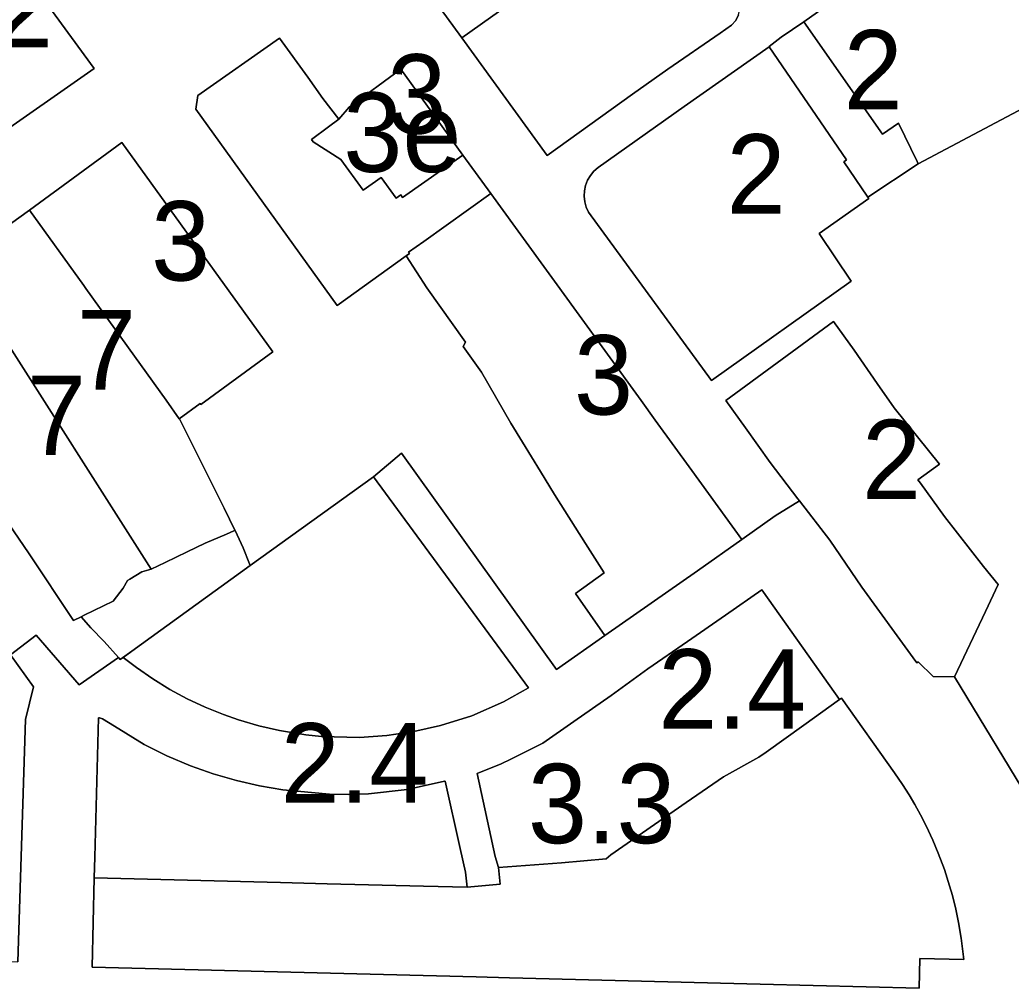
# Model space of a CAD drawing. Extents: x 598968 to 613553, y 4409678 to 4430833.
# Drawn here: x 608408.5 to 608558.2, y 4415517.6 to 4415663.9 of the extents above; entities that cross this region are included whole.
import ezdxf

# ---------------------------------------------------------------- set-up
doc = ezdxf.new("R2010")
doc.units = 0
for name, color, linetype in [('1', 7, 'Continuous'), ('SUBZONA 3e. EDIFICIS ENTRE MITGERES amb projecte especial', 7, 'Continuous'), ('ZONA 2. CARRERS DE CASES. Cases de trast', 7, 'Continuous'), ('ZONA 2.4. Ciutat jardí de mitja densitat - ANNEX III B', 7, 'Continuous'), ("ZONA 3. ILLES  D'EDIFICIS ENTRE MITGERES. EIXAMPLE.", 7, 'Continuous'), ('ZONA 3.3. Volumentría específica - ANNEX III B', 7, 'Continuous'), ('ZONA 7. CONJUNTS AMB ORDENACIONS ESPECÍFIQUES', 7, 'Continuous')]:
    doc.layers.add(name, color=color, linetype=linetype)

msp = doc.modelspace()

# ---------------------------------------------------------------- linework, layer by layer
at = {"layer": '1'}
for points in [[(608577.6388, 4415659.9159), (608549.2018, 4415644.867), (608544.1993, 4415642.2056), (608536.5794, 4415637.1455), (608536.7294, 4415636.9255), (608529.2138, 4415631.6551), (608534.0795, 4415624.4556), (608512.9448, 4415609.431), (608494.3783, 4415634.9), (608494.0303, 4415635.656), (608493.8074, 4415636.4581), (608493.7155, 4415637.2854), (608493.7569, 4415638.1168), (608493.9304, 4415638.931), (608494.2317, 4415639.7069), (608494.6531, 4415640.4248), (608495.1837, 4415641.0662), (608495.8099, 4415641.6147), (608508.8297, 4415650.8348), (608521.6796, 4415659.8749), (608521.6445, 4415659.9242), (608523.4795, 4415661.315), (608526.8877, 4415663.6594), (608562.4889, 4415688.8653)], [(608406.94, 4415674.051), (608419.7052, 4415656.5679), (608403.8649, 4415645.5793)], [(608517.0296, 4415664.7148), (608516.6096, 4415663.8448), (608515.9796, 4415663.1148), (608514.2592, 4415661.9502), (608506.3597, 4415656.4647), (608500.9998, 4415652.6847), (608488.13, 4415643.4645), (608475.2401, 4415661.2041), (608471.9401, 4415665.694)], [(608393.1412, 4415623.1231), (608409.911, 4415635.1932), (608423.8454, 4415645.4183), (608446.6784, 4415613.7497), (608435.8207, 4415605.8141), (608435.7007, 4415605.974), (608432.5334, 4415603.6723), (608432.5608, 4415603.634), (608439.3042, 4415590.1703), (608440.9603, 4415586.8244), (608440.9807, 4415586.7844), (608442.1907, 4415584.1344), (608443.1634, 4415581.7406), (608443.2718, 4415581.4737), (608461.8989, 4415594.8671), (608466.1134, 4415598.4495), (608489.5384, 4415565.76), (608496.8607, 4415570.898), (608492.3883, 4415577.2701), (608496.7401, 4415580.3855), (608493.9401, 4415584.8054), (608489.2501, 4415592.1952), (608487.1302, 4415595.6751), (608484.4202, 4415600.115), (608482.6602, 4415602.9749), (608478.2302, 4415610.6848), (608475.4502, 4415614.5847), (608475.8002, 4415615.2147), (608469.9703, 4415623.4645), (608466.8046, 4415628.2779), (608456.4211, 4415620.7551), (608435.031, 4415650.4227), (608435.3561, 4415652.5076), (608447.7078, 4415661.1547), (608451.9709, 4415655.2582), (608454.2209, 4415652.0758), (608456.6472, 4415648.9082), (608458.2303, 4415650.7539), (608466.0078, 4415656.4649), (608475.4099, 4415643.5032), (608479.6253, 4415637.6917), (608483.3374, 4415632.5741), (608489.2443, 4415624.4307), (608492.5483, 4415619.8759), (608497.2246, 4415613.4291), (608502.3143, 4415606.4122), (608504.4632, 4415603.4498), (608509.9763, 4415595.8494), (608517.559, 4415585.3959), (608522.578, 4415589.0107), (608526.2553, 4415591.2499), (608526.0044, 4415591.5766), (608521.8111, 4415597.0643), (608518.1051, 4415602.2913), (608515.1298, 4415606.4055), (608531.3795, 4415618.3656), (608534.4895, 4415614.0057), (608537.9818, 4415608.9878), (608540.5594, 4415605.286), (608547.3794, 4415596.8162), (608544.1494, 4415594.4262), (608544.5095, 4415593.9361), (608548.1516, 4415588.9013), (608554.0694, 4415581.3265), (608556.2593, 4415578.6266), (608554.3494, 4415574.5266), (608549.6895, 4415564.6566), (608561.6906, 4415544.8385)], [(608407.0624, 4415567.9754), (608410.9188, 4415570.9362), (608417.4451, 4415563.4776), (608423.3408, 4415567.6004), (608421.191, 4415570.0042), (608419.181, 4415572.0742), (608417.7298, 4415573.754), (608416.5811, 4415573.1941), (608409.8611, 4415583.2539), (608390.7884, 4415611.1929)], [(608561.6906, 4415544.8385), (608549.6895, 4415564.6566), (608546.4295, 4415564.7266), (608544.1995, 4415566.9165), (608543.9735, 4415566.7568), (608543.4295, 4415567.5265), (608541.0148, 4415570.853), (608535.6862, 4415578.2152), (608530.8306, 4415585.2916), (608526.2553, 4415591.2499), (608522.578, 4415589.0107), (608517.559, 4415585.3959), (608510.8628, 4415580.7043), (608496.8607, 4415570.898), (608489.5384, 4415565.76), (608466.1134, 4415598.4495), (608461.8989, 4415594.8671), (608485.3215, 4415562.9869), (608481.5215, 4415560.8768), (608476.7416, 4415558.7868), (608472.0017, 4415557.2967), (608467.9817, 4415556.3966), (608463.9118, 4415555.7866), (608459.7968, 4415555.5115), (608454.0319, 4415555.6464), (608451.6469, 4415555.8964), (608447.692, 4415556.5363), (608444.572, 4415557.2562), (608441.492, 4415558.1561), (608439.222, 4415558.9461), (608436.4421, 4415560.076), (608433.7221, 4415561.346), (608431.1221, 4415562.7459), (608428.5422, 4415564.3358), (608426.0822, 4415566.0608), (608424.0622, 4415567.5657), (608425.4005, 4415568.5346), (608423.6378, 4415567.2682), (608423.3964, 4415567.5382), (608423.3408, 4415567.6004), (608417.4451, 4415563.4776), (608410.9188, 4415570.9362), (608407.0624, 4415567.9754), (608410.5324, 4415563.1655), (608409.3024, 4415558.1956), (608408.1425, 4415521.596)]]:
    msp.add_lwpolyline(points, dxfattribs=at)
for points in [[(608425.4005, 4415568.5346), (608424.0622, 4415567.5657), (608426.0822, 4415566.0608), (608428.5422, 4415564.3358), (608431.1221, 4415562.7459), (608433.7221, 4415561.346), (608436.4421, 4415560.076), (608439.222, 4415558.9461), (608441.492, 4415558.1561), (608444.572, 4415557.2562), (608447.692, 4415556.5363), (608451.6469, 4415555.8964), (608454.0319, 4415555.6464), (608459.7968, 4415555.5115), (608463.9118, 4415555.7866), (608467.9817, 4415556.3966), (608472.0017, 4415557.2967), (608476.7416, 4415558.7868), (608481.5215, 4415560.8768), (608485.3215, 4415562.9869), (608461.8989, 4415594.8671), (608443.2718, 4415581.4737), (608443.2674, 4415581.4705)], [(608405.5358, 4415566.9639), (608400.7913, 4415563.4339), (608388.2915, 4415556.6838), (608388.2605, 4415556.7696), (608388.2527, 4415556.7652), (608387.3627, 4415559.1751), (608385.2102, 4415564.5075), (608383.2527, 4415569.6049), (608381.6127, 4415575.0248), (608380.6827, 4415579.9448), (608380.1461, 4415587.1097), (608379.6024, 4415587.7816), (608379.2517, 4415587.6284), (608367.8302, 4415585.857), (608367.8304, 4415522.7202), (608371.923, 4415522.4853), (608408.1425, 4415521.596), (608409.3024, 4415558.1956), (608410.5324, 4415563.1655), (608407.0624, 4415567.9754), (608406.2224, 4415567.4554)], [(608443.2718, 4415581.4737), (608443.1634, 4415581.7406), (608442.1907, 4415584.1344), (608440.9807, 4415586.7844), (608440.7969, 4415586.7057), (608439.6702, 4415586.2231), (608436.4761, 4415584.855), (608433.7414, 4415583.5403), (608430.4009, 4415581.9342), (608428.3066, 4415580.9541), (608426.9109, 4415580.5342), (608425.0668, 4415579.4278), (608424.711, 4415579.2142), (608424.0465, 4415578.0797), (608422.551, 4415576.1042), (608418.1714, 4415573.9693), (608417.7298, 4415573.754), (608419.181, 4415572.0742), (608421.191, 4415570.0042), (608423.3408, 4415567.6004), (608423.3964, 4415567.5382), (608423.6378, 4415567.2682), (608425.4005, 4415568.5346), (608443.2674, 4415581.4705)], [(608532.3165, 4415561.2214), (608532.6085, 4415561.4289), (608540.615, 4415550.1784), (608541.8336, 4415548.3914), (608542.8244, 4415546.8246), (608543.6687, 4415545.3957), (608544.5395, 4415543.816), (608545.4002, 4415542.13), (608546.4091, 4415539.9595), (608547.2229, 4415538.0148), (608548.1457, 4415535.5282), (608548.9312, 4415533.0795), (608549.349, 4415531.5986), (608549.8522, 4415529.5757), (608550.2859, 4415527.5182), (608550.6891, 4415525.1554), (608551.078, 4415521.9455), (608544.43, 4415522.1147), (608544.3155, 4415517.6161), (608520.3236, 4415518.2265), (608482.4144, 4415519.1909), (608477.3771, 4415519.319), (608419.3652, 4415520.7947), (608419.7088, 4415534.2902), (608419.7878, 4415537.3987), (608420.3241, 4415558.4667), (608420.4919, 4415558.4609), (608420.6573, 4415558.4326), (608420.8174, 4415558.3823), (608420.9693, 4415558.3108), (608422.7372, 4415557.2111), (608427.2623, 4415554.4574), (608430.6879, 4415552.7249), (608434.2201, 4415551.2219), (608437.6792, 4415549.9969), (608441.2031, 4415548.9732), (608444.6856, 4415548.1729), (608448.2075, 4415547.5693), (608455.2317, 4415546.9399), (608458.152, 4415546.8601), (608461.1322, 4415546.9656), (608466.9834, 4415547.6328), (608472.6234, 4415548.872), (608472.7339, 4415548.9024), (608475.0019, 4415538.7418), (608475.8083, 4415535.1293), (608476.0337, 4415532.8574), (608481.0092, 4415533.3512), (608480.76, 4415535.8621), (608480.2672, 4415537.5007), (608477.5272, 4415550.0305), (608481.1772, 4415551.5305), (608482.6214, 4415552.2326), (608487.4971, 4415554.6506), (608492.1609, 4415557.9172), (608497.7769, 4415561.8507), (608503.3569, 4415565.8508), (608509.3366, 4415570.0004), (608515.0877, 4415573.9917), (608520.5766, 4415577.8009), (608527.6365, 4415567.7912)]]:
    msp.add_lwpolyline(points, close=True, dxfattribs=at)
at = {"layer": 'SUBZONA 3e. EDIFICIS ENTRE MITGERES amb projecte especial'}
msp.add_lwpolyline([(608456.6472, 4415648.9082), (608454.2209, 4415652.0758), (608451.9709, 4415655.2582), (608447.7078, 4415661.1547), (608435.3561, 4415652.5076), (608435.031, 4415650.4227), (608456.4211, 4415620.7551), (608466.8046, 4415628.2779), (608467.3104, 4415628.6444), (608467.182, 4415628.8255), (608469.4741, 4415630.4587), (608479.6253, 4415637.6917), (608475.4099, 4415643.5032), (608466.2803, 4415637.1042), (608466.0103, 4415637.4942), (608465.3003, 4415637.0032), (608463.0296, 4415640.1336), (608460.343, 4415638.1873), (608456.9404, 4415642.824), (608452.7604, 4415645.5039), (608452.5181, 4415645.8394), (608455.0904, 4415647.7539)], close=True, dxfattribs=at)
at = {"layer": 'ZONA 2. CARRERS DE CASES. Cases de trast'}
for points in [[(608544.1993, 4415642.2056), (608549.2018, 4415644.867), (608577.6388, 4415659.9159), (608574.9189, 4415664.5958), (608576.1088, 4415665.2859), (608571.5688, 4415673.0591), (608573.0889, 4415674.0457), (608573.6388, 4415673.2857), (608589.3786, 4415684.5559), (608606.3484, 4415702.8959), (608596.5583, 4415713.3348), (608578.2187, 4415700.2455), (608579.5587, 4415698.3255), (608563.8489, 4415686.9654), (608562.4889, 4415688.8653), (608526.8877, 4415663.6594), (608538.8058, 4415646.6475), (608541.1893, 4415648.3254), (608544.0449, 4415642.5196)], [(608475.2401, 4415661.2041), (608488.13, 4415643.4645), (608500.9998, 4415652.6847), (608506.3597, 4415656.4647), (608514.2592, 4415661.9502), (608515.9796, 4415663.1148), (608516.6096, 4415663.8448), (608517.0296, 4415664.7148), (608517.1396, 4415665.1448), (608517.2096, 4415665.6548), (608517.1496, 4415666.6148), (608516.8496, 4415667.5248), (608516.4178, 4415668.1656), (608509.2496, 4415678.8045), (608505.0097, 4415684.9843), (608502.3697, 4415683.2343), (608499.2498, 4415681.1843), (608500.3897, 4415679.6243), (608501.4897, 4415678.1243), (608499.1201, 4415672.2043), (608498.4798, 4415670.6044), (608496.7998, 4415666.4044), (608492.0099, 4415673.2242), (608483.92, 4415667.4042)], [(608403.6097, 4415645.5), (608403.8649, 4415645.5793), (608419.7052, 4415656.5679), (608406.94, 4415674.051), (608406.7109, 4415674.1127), (608389.3811, 4415661.0925), (608395.714, 4415652.6079), (608395.7448, 4415652.6311), (608397.7489, 4415654.1331), (608397.7601, 4415654.1175), (608399.1543, 4415652.1675)], [(608544.1993, 4415642.2056), (608544.0449, 4415642.5196), (608541.1893, 4415648.3254), (608538.8058, 4415646.6475), (608526.8877, 4415663.6594), (608523.4795, 4415661.315), (608521.6445, 4415659.9242), (608521.6796, 4415659.8749), (608533.3394, 4415642.8054), (608532.9694, 4415642.4854), (608536.4897, 4415637.2781), (608536.5794, 4415637.1455)], [(608536.5794, 4415637.1455), (608536.4897, 4415637.2781), (608532.9694, 4415642.4854), (608533.3394, 4415642.8054), (608521.6796, 4415659.8749), (608508.8297, 4415650.8348), (608495.8099, 4415641.6147), (608495.1837, 4415641.0662), (608494.6531, 4415640.4248), (608494.2317, 4415639.7069), (608493.9304, 4415638.931), (608493.7569, 4415638.1168), (608493.7155, 4415637.2854), (608493.8074, 4415636.4581), (608494.0303, 4415635.656), (608494.3783, 4415634.9), (608512.9448, 4415609.431), (608534.0795, 4415624.4556), (608529.2138, 4415631.6551), (608536.7294, 4415636.9255)], [(608549.6895, 4415564.6566), (608554.3494, 4415574.5266), (608556.2593, 4415578.6266), (608554.0694, 4415581.3265), (608548.1516, 4415588.9013), (608544.5095, 4415593.9361), (608544.1494, 4415594.4262), (608547.3794, 4415596.8162), (608540.5594, 4415605.286), (608537.9818, 4415608.9878), (608534.4895, 4415614.0057), (608531.3795, 4415618.3656), (608515.1298, 4415606.4055), (608518.1051, 4415602.2913), (608521.8111, 4415597.0643), (608526.0044, 4415591.5766), (608526.2553, 4415591.2499), (608530.8306, 4415585.2916), (608535.6862, 4415578.2152), (608541.0148, 4415570.853), (608543.4295, 4415567.5265), (608543.9735, 4415566.7568), (608544.1995, 4415566.9165), (608546.4295, 4415564.7266)]]:
    msp.add_lwpolyline(points, close=True, dxfattribs=at)
at = {"layer": 'ZONA 2.4. Ciutat jardí de mitja densitat - ANNEX III B'}
for points in [[(608532.3165, 4415561.2214), (608527.6365, 4415567.7912), (608520.5766, 4415577.8009), (608515.0877, 4415573.9917), (608509.3366, 4415570.0004), (608503.3569, 4415565.8508), (608497.7769, 4415561.8507), (608492.1609, 4415557.9172), (608487.4971, 4415554.6506), (608482.6214, 4415552.2326), (608481.1772, 4415551.5305), (608477.5272, 4415550.0305), (608480.2672, 4415537.5007), (608480.76, 4415535.8621), (608490.2771, 4415536.5709), (608497.017, 4415537.141), (608497.737, 4415537.761), (608509.1469, 4415545.6511), (608514.7568, 4415549.5412), (608520.1261, 4415552.5221), (608521.2128, 4415553.2963), (608526.9105, 4415557.3629)], [(608476.0337, 4415532.8574), (608475.8083, 4415535.1293), (608475.0019, 4415538.7418), (608472.7339, 4415548.9024), (608472.6234, 4415548.872), (608466.9834, 4415547.6328), (608461.1322, 4415546.9656), (608458.152, 4415546.8601), (608455.2317, 4415546.9399), (608448.2075, 4415547.5693), (608444.6856, 4415548.1729), (608441.2031, 4415548.9732), (608437.6792, 4415549.9969), (608434.2201, 4415551.2219), (608430.6879, 4415552.7249), (608427.2623, 4415554.4574), (608422.7372, 4415557.2111), (608420.9693, 4415558.3108), (608420.8174, 4415558.3823), (608420.6573, 4415558.4326), (608420.4919, 4415558.4609), (608420.3241, 4415558.4667), (608419.7878, 4415537.3987), (608419.7088, 4415534.2902), (608433.78, 4415533.9323), (608447.8513, 4415533.5743), (608454.8869, 4415533.3953), (608469.4217, 4415533.0256)]]:
    msp.add_lwpolyline(points, close=True, dxfattribs=at)
at = {"layer": "ZONA 3. ILLES  D'EDIFICIS ENTRE MITGERES. EIXAMPLE."}
for points in [[(608505.0097, 4415684.9843), (608503.4297, 4415687.3043), (608501.6021, 4415690.0048), (608499.5659, 4415693.0136), (608497.693, 4415695.722), (608466.8746, 4415674.5267), (608466.7902, 4415673.9238), (608466.7886, 4415673.4447), (608466.8202, 4415673.0238), (608466.8902, 4415672.6338), (608467.3756, 4415671.9611), (608468.8601, 4415669.9039), (608471.9401, 4415665.694), (608475.2401, 4415661.2041), (608483.92, 4415667.4042), (608492.0099, 4415673.2242), (608496.7998, 4415666.4044), (608498.4798, 4415670.6044), (608499.1201, 4415672.2043), (608501.4897, 4415678.1243), (608500.3897, 4415679.6243), (608499.2498, 4415681.1843), (608502.3697, 4415683.2343)], [(608475.4099, 4415643.5032), (608466.0078, 4415656.4649), (608458.2303, 4415650.7539), (608456.6472, 4415648.9082), (608455.0904, 4415647.7539), (608452.5181, 4415645.8394), (608452.7604, 4415645.5039), (608456.9404, 4415642.824), (608460.343, 4415638.1873), (608463.0296, 4415640.1336), (608465.3003, 4415637.0032), (608466.0103, 4415637.4942), (608466.2803, 4415637.1042)], [(608432.5334, 4415603.6723), (608435.7007, 4415605.974), (608435.8207, 4415605.8141), (608446.6784, 4415613.7497), (608423.8454, 4415645.4183), (608409.911, 4415635.1932), (608418.1505, 4415623.7733), (608418.446, 4415623.3635), (608422.8103, 4415617.2633), (608430.5408, 4415606.4539)], [(608517.559, 4415585.3959), (608509.9763, 4415595.8494), (608504.4632, 4415603.4498), (608502.3143, 4415606.4122), (608497.2246, 4415613.4291), (608492.5483, 4415619.8759), (608489.2443, 4415624.4307), (608483.3374, 4415632.5741), (608479.6253, 4415637.6917), (608469.4741, 4415630.4587), (608467.182, 4415628.8255), (608467.3104, 4415628.6444), (608466.8046, 4415628.2779), (608469.9703, 4415623.4645), (608475.8002, 4415615.2147), (608475.4502, 4415614.5847), (608478.2302, 4415610.6848), (608482.6602, 4415602.9749), (608484.4202, 4415600.115), (608487.1302, 4415595.6751), (608489.2501, 4415592.1952), (608493.9401, 4415584.8054), (608496.7401, 4415580.3855), (608492.3883, 4415577.2701), (608496.8607, 4415570.898), (608510.8628, 4415580.7043)]]:
    msp.add_lwpolyline(points, close=True, dxfattribs=at)
at = {"layer": 'ZONA 3.3. Volumentría específica - ANNEX III B'}
msp.add_lwpolyline([(608419.7088, 4415534.2902), (608419.3652, 4415520.7947), (608477.3771, 4415519.319), (608482.4144, 4415519.1909), (608520.3236, 4415518.2265), (608544.3155, 4415517.6161), (608544.43, 4415522.1147), (608551.078, 4415521.9455), (608550.6891, 4415525.1554), (608550.2859, 4415527.5182), (608549.8522, 4415529.5757), (608549.349, 4415531.5986), (608548.9312, 4415533.0795), (608548.1457, 4415535.5282), (608547.2229, 4415538.0148), (608546.4091, 4415539.9595), (608545.4002, 4415542.13), (608544.5395, 4415543.816), (608543.6687, 4415545.3957), (608542.8244, 4415546.8246), (608541.8336, 4415548.3914), (608540.615, 4415550.1784), (608532.6085, 4415561.4289), (608532.3165, 4415561.2214), (608526.9105, 4415557.3629), (608521.2128, 4415553.2963), (608520.1261, 4415552.5221), (608514.7568, 4415549.5412), (608509.1469, 4415545.6511), (608497.737, 4415537.761), (608497.017, 4415537.141), (608490.2771, 4415536.5709), (608480.76, 4415535.8621), (608481.0092, 4415533.3512), (608476.0337, 4415532.8574), (608469.4217, 4415533.0256), (608454.8869, 4415533.3953), (608447.8513, 4415533.5743), (608433.78, 4415533.9323)], close=True, dxfattribs=at)
at = {"layer": 'ZONA 7. CONJUNTS AMB ORDENACIONS ESPECÍFIQUES'}
for points in [[(608432.5334, 4415603.6723), (608430.5408, 4415606.4539), (608422.8103, 4415617.2633), (608418.446, 4415623.3635), (608418.1505, 4415623.7733), (608409.911, 4415635.1932), (608393.1412, 4415623.1231), (608397.2142, 4415617.5055), (608397.6888, 4415616.8509), (608404.7162, 4415617.92), (608428.3066, 4415580.9541), (608430.4009, 4415581.9342), (608433.7414, 4415583.5403), (608436.4761, 4415584.855), (608439.6702, 4415586.2231), (608440.7969, 4415586.7057), (608440.9807, 4415586.7844), (608440.9603, 4415586.8244), (608439.3042, 4415590.1703), (608432.5608, 4415603.634)], [(608428.3066, 4415580.9541), (608404.7162, 4415617.92), (608397.6888, 4415616.8509), (608397.2142, 4415617.5055), (608393.1412, 4415623.1231), (608390.7884, 4415611.1929), (608409.8611, 4415583.2539), (608416.5811, 4415573.1941), (608417.7298, 4415573.754), (608418.1714, 4415573.9693), (608422.551, 4415576.1042), (608424.0465, 4415578.0797), (608424.711, 4415579.2142), (608425.0668, 4415579.4278), (608426.9109, 4415580.5342)]]:
    msp.add_lwpolyline(points, close=True, dxfattribs=at)

# ---------------------------------------------------------------- texts
at = {"layer": 'SUBZONA 3e. EDIFICIS ENTRE MITGERES amb projecte especial'}
msp.add_text('3e', height=12, dxfattribs=at).set_placement((608457.3282, 4415640.9549))
at = {"layer": 'ZONA 2. CARRERS DE CASES. Cases de trast'}
for p in [(608404.5431, 4415659.8064), (608532.9219, 4415650.4024), (608515.2224, 4415634.653), (608535.6946, 4415591.5111)]:
    msp.add_text('2', height=12, dxfattribs=at).set_placement(p)
at = {"layer": 'ZONA 2.4. Ciutat jardí de mitja densitat - ANNEX III B'}
for p in [(608504.9219, 4415556.8315), (608447.8712, 4415545.6621)]:
    msp.add_text('2.4', height=12, dxfattribs=at).set_placement(p)
at = {"layer": "ZONA 3. ILLES  D'EDIFICIS ENTRE MITGERES. EIXAMPLE."}
for p in [(608463.964, 4415646.7341), (608428.2947, 4415624.5453), (608492.1818, 4415604.2949)]:
    msp.add_text('3', height=12, dxfattribs=at).set_placement(p)
at = {"layer": 'ZONA 3.3. Volumentría específica - ANNEX III B'}
msp.add_text('3.3', height=12, dxfattribs=at).set_placement((608485.2216, 4415539.5225))
at = {"layer": 'ZONA 7. CONJUNTS AMB ORDENACIONS ESPECÍFIQUES'}
for p in [(608417.061, 4415608.0736), (608409.5475, 4415598.1586)]:
    msp.add_text('7', height=12, dxfattribs=at).set_placement(p)

doc.saveas('drawing.dxf')
